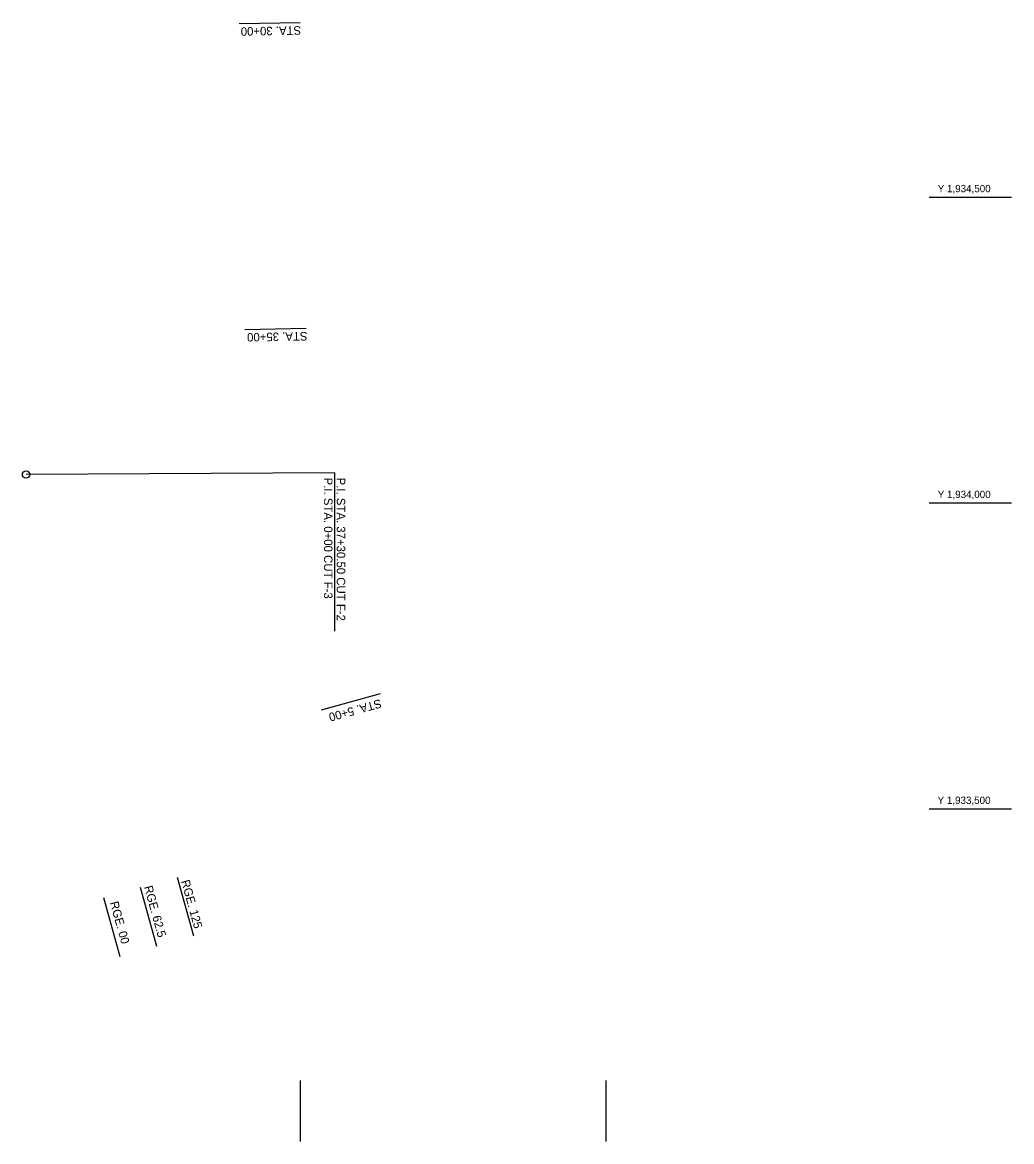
# Model space of a CAD drawing. Extents: x 585414 to 588664, y 1932755 to 1936856.
# Drawn here: x 587046 to 588664, y 1932956 to 1934786 of the extents above; entities that cross this region are included whole.
import ezdxf

# ---------------------------------------------------------------- set-up
doc = ezdxf.new("R2010")
doc.units = 0
for name, color, linetype in [('V-ANNO-KEYN', 7, 'Continuous'), ('V-ANNO-MASK', 7, 'Continuous'), ('V-ANNO-SYMB', 7, 'Continuous'), ('V-COMM-OVHD', 7, 'Continuous')]:
    doc.layers.add(name, color=color, linetype=linetype)

msp = doc.modelspace()

# ---------------------------------------------------------------- linework, layer by layer
at = {"layer": 'V-ANNO-KEYN'}
for p, q in [((588528.7, 1934500), (588663.7, 1934500)), ((588528.7, 1934000), (588663.7, 1934000)), ((588528.7, 1933500), (588663.7, 1933500)), ((587500, 1933056), (587500, 1932956)), ((588000, 1933056), (588000, 1932956))]:
    msp.add_line(p, q, dxfattribs=at)
at = {"layer": 'V-ANNO-SYMB'}
for p, q in [((587238.4, 1933371.9), (587265.1, 1933275.5)), ((587298.7, 1933388.5), (587325.4, 1933292.2)), ((587178.2, 1933355.2), (587204.9, 1933258.8))]:
    msp.add_line(p, q, dxfattribs=at)
at = {"layer": 'V-COMM-OVHD'}
for p, q in [((587400.1, 1934783.7), (587500.1, 1934785.6)), ((587409.6, 1934283.8), (587509.6, 1934285.7)), ((587556.3, 1934049.4), (587051.6, 1934046.5)), ((587556.3, 1934049.4), (587556.3, 1933790.5)), ((587630.8, 1933688.1), (587534.4, 1933661.4))]:
    msp.add_line(p, q, dxfattribs=at)
msp.add_circle((587051.6, 1934046.5), 6, dxfattribs=at)

# ---------------------------------------------------------------- texts
at = {"layer": 'V-ANNO-MASK'}
for s, p in [('Y 1,934,500', (588542.8, 1934508)), ('Y 1,934,000', (588542.8, 1934008)), ('Y 1,933,500', (588542.6, 1933508))]:
    msp.add_text(s, height=12, dxfattribs=at).set_placement(p)
at = {"layer": 'V-ANNO-SYMB'}
for s, p in [('RGE. 62.5', (587244.5, 1933372.4)), ('RGE. 125', (587305.1, 1933381.8)), ('RGE. 00', (587188.7, 1933346.7))]:
    msp.add_text(s, height=13.92, rotation=285.4813, dxfattribs=at).set_placement(p)
at = {"layer": 'V-COMM-OVHD'}
for s, rotation, p in [('STA. 30+00', 181.0918, (587501.4, 1934779.5)), ('STA. 35+00', 181.0918, (587511.8, 1934279.6)), ('P.I. STA. 0+00 CUT F-3', 270, (587538.9, 1934041.5)), ('P.I. STA. 37+30.50 CUT F-2', 270, (587559.8, 1934041.5)), ('STA. 5+00', 195.4813, (587630.8, 1933679.5))]:
    msp.add_text(s, height=13.92, rotation=rotation, dxfattribs=at).set_placement(p)

doc.saveas('drawing.dxf')
